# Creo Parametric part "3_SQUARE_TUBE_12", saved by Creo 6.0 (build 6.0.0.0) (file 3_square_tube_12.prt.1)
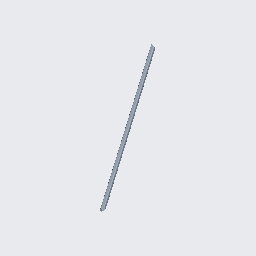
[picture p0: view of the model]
Units: Custom; MM, KILOGRAM, SECS
Materials in the file: STEEL

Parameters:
  BUW_NAME = "SQUARE TUBE"
  BUW_TYPE = "DIN EN 10219"
  BUW_SIZE = "25x25x3.0"
  BUW_LENGTH_STR = "1235"
  PTC_MATERIAL_NAME = "STEEL"
  BUW_PROFIL_TYPE = "square_tube"
  BUW_PROFILE_PATH = "parts//profiles/steel_beams_mm/"
  BUW_PROFILE_NAME_LANG = "SQUARE TUBE"
  BUW_TAB_SEL_INFO = "-2 TYPE DIN_EN_10219-1997 SIZE_DINEN_10219 25x25x3.0"
  NAMING = "SQUARE TUBE"
  DESIGNATION = "DIN EN 10219 25x25x3.0 x 1235"
  PROFIL_RASTER_POS = "X_0"
  BUW_OBJECT_ROLE = "PROFIL_SYSTEM_BORE_END_POINTS"
  PRO_UNIT_SYS = "Custom"

Other parameters: BUW_LENGTH, LENGTH, BUW_LENGTH_Z_MIN_PARAM, D8, D93, D94, d26, d8, d93, d94, d98, D98, SHEAR_MODULUS, THERM_EXPANSION_REF_TEMPERATURE, STRUCTURAL_DAMPING_COEFFICIENT, STRESS_LIMIT_FOR_TENSION, STRESS_LIMIT_FOR_COMPRESSION, STRESS_LIMIT_FOR_SHEAR, EMISSIVITY

Created from: SQUARE_TUBE.PRT

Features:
  1. datum plane "YZ"
  2. datum plane "XZ"
  3. datum plane "XY"
  4. coordinate system
  5. coordinate system
  6. coordinate system
  7. coordinate system
  8. datum plane "DTM3"
  9. datum plane "DTM4"
  10. datum plane "DTM5"
  11. protrusion
  12. round
  13. round
  14. datum axis
  15. datum point "PNT0"
  16. datum point

Other named items: PROFIL_CUT_QUILT, PROFILE_LENGTH_DIM, CONTACT_SURF_3, CONTACT_SURF_2, CONTACT_SURF_1, CONTACT_SURF_0, E, START_SURFACE, END_SURFACE, SIDE_SURF_3, SIDE_SURF_0, SIDE_SURF_1, SIDE_SURF_2, EDGE_7_S, EDGE_7_E, EDGE_1_S, EDGE_1_E, EDGE_3_S, EDGE_3_E, EDGE_5_S, EDGE_5_E, EDGE_6_S, EDGE_4_S, EDGE_2_S, EDGE_0_S, EDGE_6_E, EDGE_4_E, EDGE_2_E, EDGE_0_E, CS0, CS_S, CS_E, CS3

Named dimensions: X_ROT_S, Y_ROT_S, Z_OFF_S, X_ROT_E, Y_ROT_E, Z_OFF_E, PC_L, BUW_LENGTH_Z_MIN, BUW_LENGTH_DIM

Layers: 00_PROFIL_DATUM, 00_PROFIL_DRW_HIDE, 00_PROFIL_END_CSYS, 00_PROFIL_GEOMETRY, 00_PROFIL_QUILT, 00_PROFIL_SIZE_NOTE

Surfaces: 16 plane, 12 cylinder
